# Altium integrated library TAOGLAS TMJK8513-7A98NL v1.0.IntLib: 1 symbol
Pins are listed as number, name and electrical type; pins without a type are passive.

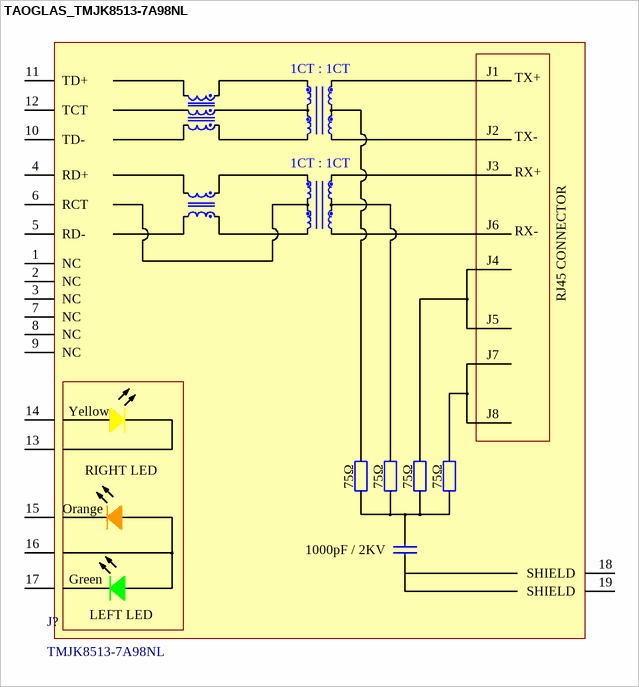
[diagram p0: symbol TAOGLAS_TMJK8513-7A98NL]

## TAOGLAS_TMJK8513-7A98NL
designator J?, comment TMJK8513-7A98NL
RJ45 connector with integrated magnetics 10/100 Base-T Single Port Tab-UP with right angle THT mount and LEDs; ComponentLibStatus: Created; MFG: Taoglas; Temp_High: +85C; Temp_Low: -40C
footprint TAOGLAS_TMJK8513-7A98NL (RJ45 connector with integrated magnetics 10/100 Base-T Single Port Tab-UP with right angle THT mount and LEDs)
pins: 1 NC, 2 NC, 3 NC, 4 RD+, 5 RD-, 6 RCT, 7 NC, 8 NC, 9 NC, 10 TD-, 11 TD+, 12 TCT, 13, 14, 15, 16, 17, 18 SHIELD, 19 SHIELD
